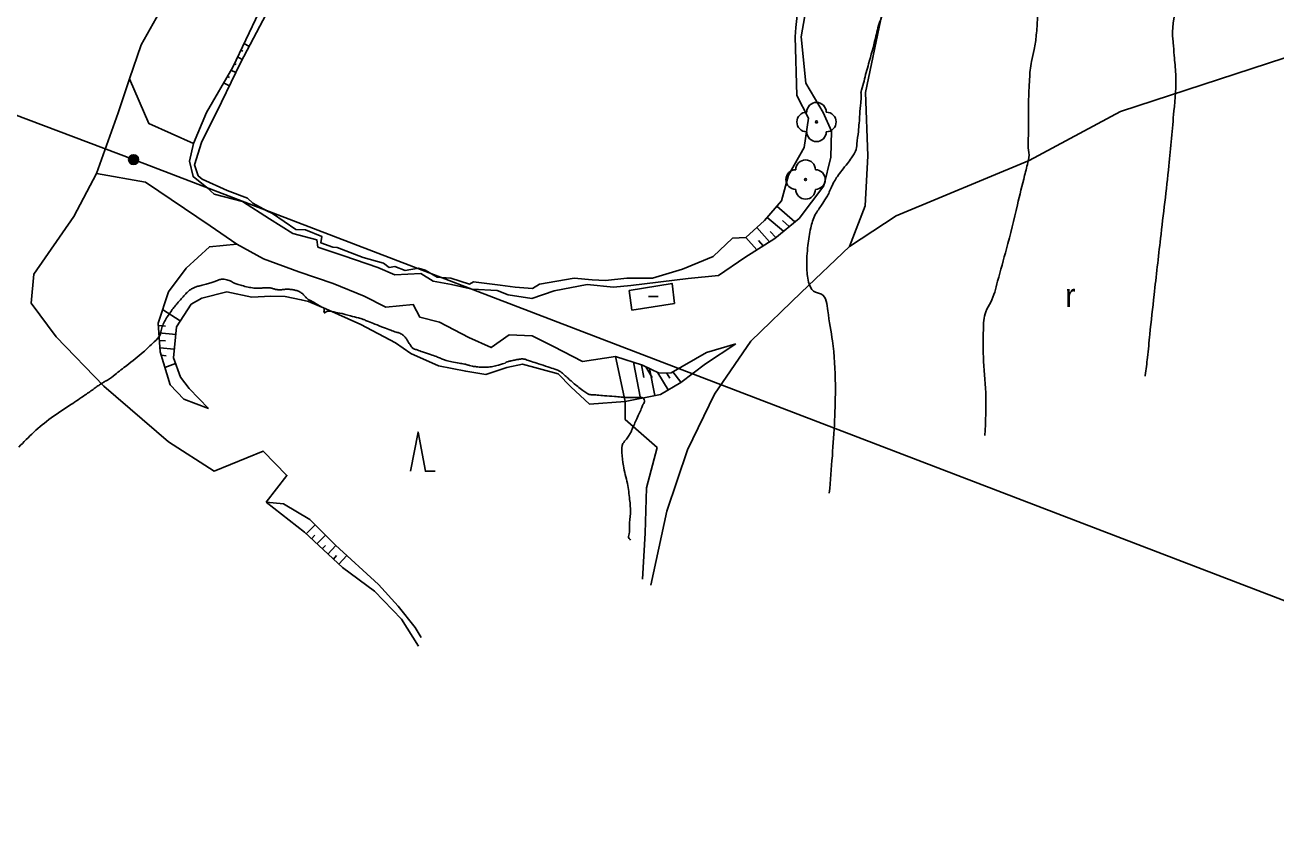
# Model space of a CAD drawing. Extents: x -475575 to -473225, y -1116053 to -1114104.
# Drawn here: x -474036.8 to -473909.2, y -1115920.9 to -1115838.9 of the extents above; entities that cross this region are included whole.
import ezdxf

# ---------------------------------------------------------------- set-up
doc = ezdxf.new("R2010")
doc.units = 0
doc.layers.add('Vrstevnice_vedlejsi', color=7, linetype='Continuous')
doc.layers.add('Vrstva_10', color=7, linetype='Continuous')

msp = doc.modelspace()

# ---------------------------------------------------------------- linework, layer by layer
at = {"layer": 'Vrstevnice_vedlejsi'}
for points in [[(-473849.08800000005, -1115665.384), (-473849.911, -1115667.105), (-473850.824, -1115668.952), (-473851.82800000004, -1115670.9270000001), (-473852.924, -1115673.0280000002), (-473853.94800000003, -1115674.8290000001), (-473854.9, -1115676.33), (-473855.78, -1115677.531), (-473856.701, -1115678.789), (-473857.663, -1115680.104), (-473858.666, -1115681.475), (-473858.526, -1115685.303), (-473857.244, -1115691.5860000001), (-473854.819, -1115700.3260000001), (-473853.38700000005, -1115707.367), (-473852.94700000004, -1115712.7110000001), (-473853.50100000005, -1115716.355), (-473856.753, -1115721.199), (-473862.70300000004, -1115727.2410000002), (-473871.352, -1115734.4810000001), (-473878.193, -1115740.057), (-473883.22900000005, -1115743.967), (-473886.457, -1115746.213), (-473888.69200000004, -1115748.0080000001), (-473889.93200000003, -1115749.3530000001), (-473890.178, -1115750.2480000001), (-473890.522, -1115751.3660000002), (-473890.96400000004, -1115752.709), (-473891.505, -1115754.276), (-473892.082, -1115755.84), (-473892.694, -1115757.399), (-473893.341, -1115758.955), (-473893.989, -1115760.3930000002), (-473894.63700000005, -1115761.712), (-473895.287, -1115762.912), (-473896.631, -1115765.4980000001), (-473898.67000000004, -1115769.469), (-473901.40400000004, -1115774.824), (-473903.569, -1115778.895), (-473905.163, -1115781.681), (-473906.18700000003, -1115783.182), (-473907.574, -1115785.885), (-473909.324, -1115789.789), (-473911.438, -1115794.894), (-473913.02400000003, -1115798.887), (-473914.082, -1115801.766), (-473914.614, -1115803.531), (-473915, -1115805.0150000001), (-473915.24100000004, -1115806.219), (-473915.337, -1115807.141), (-473915.885, -1115811.303), (-473916.884, -1115818.703), (-473918.335, -1115829.343), (-473919.30100000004, -1115836.442), (-473919.78400000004, -1115840.002), (-473919.783, -1115840.022), (-473919.73000000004, -1115840.673), (-473919.62600000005, -1115841.955), (-473919.47000000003, -1115843.869), (-473919.651, -1115847.62), (-473920.169, -1115853.208), (-473921.02400000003, -1115860.634), (-473921.672, -1115866.3660000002), (-473922.114, -1115870.405), (-473922.34900000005, -1115872.7510000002), (-473922.57300000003, -1115874.585), (-473922.581296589, -1115874.648507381)], [(-473938.93362807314, -1115880.720956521), (-473938.84300000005, -1115876.351), (-473939.08400000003, -1115872.702), (-473939.079, -1115869.948), (-473938.82800000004, -1115868.09), (-473938.331, -1115867.1260000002), (-473937.63, -1115864.989), (-473936.72400000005, -1115861.678), (-473935.614, -1115857.193), (-473934.87200000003, -1115854.198), (-473934.5, -1115852.693), (-473934.49700000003, -1115852.679), (-473934.495, -1115852.666), (-473934.493, -1115852.654), (-473934.492, -1115852.6430000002), (-473934.49000000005, -1115852.631), (-473934.488, -1115852.618), (-473934.484, -1115852.605), (-473934.48000000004, -1115851.618), (-473934.477, -1115849.658), (-473934.472, -1115846.723), (-473934.374, -1115844.361), (-473934.18000000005, -1115842.5720000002), (-473933.89200000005, -1115841.355), (-473933.68700000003, -1115839.875), (-473933.565, -1115838.1330000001), (-473933.525, -1115836.127), (-473933.31, -1115834.3360000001), (-473932.92100000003, -1115832.7580000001), (-473932.357, -1115831.395), (-473931.79500000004, -1115829.879), (-473931.23500000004, -1115828.213), (-473930.679, -1115826.395), (-473930.08300000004, -1115822.996), (-473929.44700000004, -1115818.016), (-473928.77300000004, -1115811.455), (-473928.24700000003, -1115806.61), (-473927.87, -1115803.4810000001), (-473927.64200000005, -1115802.0690000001), (-473927.36600000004, -1115800.502), (-473927.042, -1115798.78), (-473926.67100000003, -1115796.9030000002), (-473926.27900000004, -1115794.601), (-473925.86600000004, -1115791.872), (-473925.43200000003, -1115788.716), (-473925.036, -1115786.321), (-473924.67600000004, -1115784.686), (-473924.35400000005, -1115783.811), (-473923.89900000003, -1115782.575), (-473923.31100000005, -1115780.977), (-473922.59, -1115779.017), (-473922.106, -1115777.688), (-473921.859, -1115776.9910000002), (-473921.84900000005, -1115776.924), (-473921.84, -1115776.834), (-473921.832, -1115776.722), (-473921.824, -1115776.587), (-473921.80000000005, -1115776.462), (-473921.759, -1115776.348), (-473921.701, -1115776.244), (-473921.177, -1115775.487), (-473920.18600000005, -1115774.0790000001), (-473918.72900000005, -1115772.0180000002), (-473917.73000000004, -1115770.605), (-473917.19, -1115769.838), (-473917.108, -1115769.718), (-473917.05100000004, -1115769.632), (-473917.01800000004, -1115769.5820000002), (-473917.01, -1115769.566), (-473916.50200000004, -1115768.6260000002), (-473915.494, -1115766.762), (-473913.98600000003, -1115763.9740000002), (-473912.48000000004, -1115760.911), (-473911.1822816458, -1115758.0507802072)], [(-473954.7894387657, -1115886.609022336), (-473954.481, -1115882.779), (-473954.17500000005, -1115875.538), (-473954.47000000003, -1115871.0760000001), (-473954.938, -1115868), (-473955.579, -1115866.308), (-473956.39300000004, -1115866.0010000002), (-473956.897, -1115865.068), (-473957.09, -1115863.51), (-473956.973, -1115861.3260000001), (-473956.68100000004, -1115859.549), (-473956.216, -1115858.1770000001), (-473955.575, -1115857.21), (-473955.12, -1115856.493), (-473954.84900000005, -1115856.024), (-473954.764, -1115855.8050000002), (-473954.64, -1115855.527), (-473954.47900000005, -1115855.19), (-473954.27900000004, -1115854.796), (-473953.957, -1115854.2950000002), (-473953.51300000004, -1115853.6870000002), (-473952.946, -1115852.9710000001), (-473952.52300000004, -1115852.405), (-473952.245, -1115851.989), (-473952.11000000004, -1115851.723), (-473951.971, -1115850.965), (-473951.82700000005, -1115849.715), (-473951.68000000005, -1115847.972), (-473951.58400000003, -1115846.779), (-473951.54000000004, -1115846.135), (-473951.547, -1115846.041), (-473951.553, -1115845.946), (-473951.55700000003, -1115845.851), (-473951.559, -1115845.754), (-473951.55100000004, -1115845.661), (-473951.532, -1115845.5720000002), (-473951.50100000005, -1115845.487), (-473951.25100000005, -1115844.567), (-473950.78, -1115842.81), (-473950.08800000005, -1115840.219), (-473949.62700000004, -1115838.49), (-473949.396, -1115837.6260000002), (-473949.396, -1115837.624), (-473949.396, -1115837.622), (-473949.395, -1115837.62), (-473949.39400000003, -1115837.617), (-473949.146, -1115836.566), (-473948.64900000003, -1115834.467), (-473947.90400000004, -1115831.318), (-473947.407, -1115829.219), (-473947.158, -1115828.1700000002), (-473947.158, -1115828.169), (-473947.158, -1115828.168), (-473947.158, -1115828.1670000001), (-473947.157, -1115828.166), (-473947.157, -1115828.164), (-473947.157, -1115828.163), (-473947.156, -1115828.161), (-473946.77800000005, -1115827.246), (-473946.021, -1115825.4170000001), (-473944.88700000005, -1115822.675), (-473944.13, -1115820.8460000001), (-473943.75200000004, -1115819.931), (-473943.75200000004, -1115819.9300000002), (-473943.75100000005, -1115819.929), (-473943.75, -1115819.928), (-473943.749, -1115819.9270000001), (-473943.748, -1115819.926), (-473943.74700000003, -1115819.925), (-473943.74600000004, -1115819.925), (-473943.461, -1115819.017), (-473942.89200000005, -1115817.2010000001), (-473942.038, -1115814.4780000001), (-473941.451, -1115812.604), (-473941.13, -1115811.5790000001), (-473941.076, -1115811.4030000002), (-473941.047, -1115811.137), (-473941.041, -1115810.781)], [(-473994.22900000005, -1115872.945), (-473994.422, -1115872.837), (-473994.824, -1115872.673), (-473995.434, -1115872.455), (-473996.253, -1115872.183), (-473996.82700000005, -1115871.9880000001), (-473997.157, -1115871.872), (-473997.243, -1115871.834), (-473997.395, -1115871.654), (-473997.613, -1115871.3320000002), (-473997.897, -1115870.867), (-473998.216, -1115870.519), (-473998.569, -1115870.287), (-473998.956, -1115870.172), (-473999.51, -1115869.977), (-474000.22900000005, -1115869.703), (-474001.114, -1115869.35), (-474001.759, -1115869.093), (-474002.162, -1115868.933), (-474002.325, -1115868.869), (-474002.80600000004, -1115868.73), (-474003.60500000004, -1115868.516), (-474004.722, -1115868.226), (-474005.52400000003, -1115868.074), (-474006.009, -1115868.0590000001), (-474006.179, -1115868.181), (-474006.281, -1115868.203), (-474006.31600000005, -1115868.124), (-474006.282, -1115867.9440000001), (-474006.292, -1115867.8090000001), (-474006.346, -1115867.719), (-474006.444, -1115867.675), (-474006.63800000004, -1115867.566), (-474006.929, -1115867.3930000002), (-474007.31600000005, -1115867.1570000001), (-474007.601, -1115866.992), (-474007.783, -1115866.899), (-474007.864, -1115866.877), (-474008.00100000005, -1115866.771), (-474008.19700000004, -1115866.578), (-474008.45, -1115866.301), (-474008.745, -1115866.087), (-474009.082, -1115865.9370000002), (-474009.461, -1115865.851), (-474009.846, -1115865.807), (-474010.238, -1115865.806), (-474010.63700000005, -1115865.848), (-474011, -1115865.844), (-474011.32700000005, -1115865.7920000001), (-474011.618, -1115865.695), (-474011.98000000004, -1115865.646), (-474012.413, -1115865.647), (-474012.916, -1115865.696), (-474013.461, -1115865.675), (-474014.049, -1115865.583), (-474014.678, -1115865.4200000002), (-474015.17100000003, -1115865.27), (-474015.52800000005, -1115865.131), (-474015.75, -1115865.0050000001), (-474015.983, -1115864.9030000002), (-474016.227, -1115864.8260000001), (-474016.483, -1115864.774), (-474016.772, -1115864.786), (-474017.09400000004, -1115864.862), (-474017.449, -1115865.003), (-474017.859, -1115865.1400000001), (-474018.326, -1115865.276), (-474018.848, -1115865.408), (-474019.271, -1115865.534), (-474019.596, -1115865.654), (-474019.82200000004, -1115865.7680000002), (-474020.064, -1115865.943), (-474020.32200000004, -1115866.179), (-474020.596, -1115866.477), (-474020.878, -1115866.793), (-474021.169, -1115867.1260000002), (-474021.47000000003, -1115867.477), (-474021.78, -1115867.8800000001), (-474022.101, -1115868.3360000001), (-474022.43200000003, -1115868.844), (-474022.69100000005, -1115869.354), (-474022.878, -1115869.867), (-474022.994, -1115870.3830000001), (-474023.62100000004, -1115871.169), (-474024.76, -1115872.2280000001), (-474026.411, -1115873.558), (-474027.617, -1115874.5010000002), (-474028.378, -1115875.058), (-474028.693, -1115875.2280000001), (-474029.02300000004, -1115875.4300000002), (-474029.369, -1115875.663), (-474029.73000000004, -1115875.929), (-474030.64400000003, -1115876.561), (-474032.11000000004, -1115877.56), (-474034.128, -1115878.926), (-474035.902, -1115880.3760000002), (-474037.43100000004, -1115881.909)], [(-473975.06290085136, -1115891.391556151), (-473975.157, -1115891.245), (-473975.20800000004, -1115891.202), (-473975.211, -1115890.757), (-473975.166, -1115889.909), (-473975.07300000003, -1115888.6600000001), (-473975.145, -1115887.225), (-473975.381, -1115885.605), (-473975.783, -1115883.799), (-473975.93200000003, -1115882.442), (-473975.82800000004, -1115881.534), (-473975.471, -1115881.075), (-473975.196, -1115880.679), (-473975.004, -1115880.345), (-473974.89300000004, -1115880.074), (-473974.723, -1115879.681), (-473974.49100000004, -1115879.166), (-473974.2, -1115878.5280000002), (-473973.957, -1115877.984), (-473973.76300000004, -1115877.533), (-473973.618, -1115877.175), (-473973.738, -1115876.941), (-473974.124, -1115876.831), (-473974.775, -1115876.844), (-473975.239, -1115876.848), (-473975.516, -1115876.843), (-473975.60500000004, -1115876.827), (-473976.00100000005, -1115876.79), (-473976.70300000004, -1115876.7310000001), (-473977.712, -1115876.651), (-473978.46, -1115876.593), (-473978.94800000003, -1115876.558), (-473979.17500000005, -1115876.5450000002), (-473979.5, -1115876.402), (-473979.92100000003, -1115876.128), (-473980.44, -1115875.7240000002), (-473980.911, -1115875.337), (-473981.335, -1115874.967), (-473981.712, -1115874.6160000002), (-473982.00800000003, -1115874.355), (-473982.22500000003, -1115874.1840000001), (-473982.36100000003, -1115874.105), (-473982.777, -1115873.948), (-473983.473, -1115873.713), (-473984.45, -1115873.4000000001), (-473985.151, -1115873.171), (-473985.57800000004, -1115873.026), (-473985.73000000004, -1115872.965), (-473985.879, -1115872.925), (-473986.025, -1115872.904), (-473986.168, -1115872.9030000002), (-473986.408, -1115872.933), (-473986.745, -1115872.993), (-473987.179, -1115873.085), (-473987.50700000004, -1115873.1700000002), (-473987.72900000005, -1115873.2510000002), (-473987.84500000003, -1115873.3260000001), (-473988.113, -1115873.421), (-473988.53400000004, -1115873.536), (-473989.107, -1115873.671), (-473989.669, -1115873.744), (-473990.221, -1115873.754), (-473990.764, -1115873.702), (-473991.179, -1115873.647), (-473991.466, -1115873.588), (-473991.62700000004, -1115873.5250000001), (-473991.984, -1115873.438), (-473992.537, -1115873.327), (-473993.286, -1115873.19), (-473993.85000000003, -1115873.063), (-473994.22900000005, -1115872.945)]]:
    msp.add_spline(points, degree=3, dxfattribs=at)
at = {"layer": 'Vrstva_10'}
for p, q in [((-474014.4609299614, -1115840.7491937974), (-474013.9345895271, -1115841.0286887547)), ((-474015.1124322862, -1115842.1016026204), (-474014.63808012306, -1115842.3534909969)), ((-474014.78668112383, -1115841.425398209), (-474014.5865426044, -1115841.5316748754)), ((-474015.7980128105, -1115843.4601263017), (-474015.29955235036, -1115843.6995289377)), ((-474015.4472291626, -1115842.7965844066), (-474015.2582766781, -1115842.8873352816)), ((-474016.55470474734, -1115844.760734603), (-474015.9489611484, -1115845.0516636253)), ((-474016.17635877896, -1115844.1104304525), (-474015.9555179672, -1115844.216496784)), ((-473958.28931128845, -1115858.9221845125), (-473960.1345433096, -1115857.331656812)), ((-473959.465230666, -1115859.888914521), (-473961.1138857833, -1115858.4678294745)), ((-473958.87727097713, -1115859.4055495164), (-473959.5760484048, -1115858.803226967)), ((-473960.88452292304, -1115860.9537840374), (-473962.1892148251, -1115859.510246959)), ((-473960.2516760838, -1115860.5354557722), (-473960.80412613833, -1115859.9242140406)), ((-473962.17069991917, -1115861.7676929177), (-473963.302, -1115860.516)), ((-473961.5276357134, -1115861.36075385), (-473962.01483279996, -1115860.8217093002)), ((-473973.23263136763, -1115866.5248458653), (-473972.23263136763, -1115866.5248458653)), ((-474022.7585123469, -1115867.8681098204), (-474020.9656823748, -1115869.0342220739)), ((-474023.2030597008, -1115869.4959401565), (-474022.46715973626, -1115869.5643088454)), ((-474023.15249645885, -1115870.2538675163), (-474021.4326896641, -1115870.4136459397)), ((-474023.1019332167, -1115871.011794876), (-474022.4619877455, -1115871.0712489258)), ((-474023.0513699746, -1115871.7697222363), (-474021.57144941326, -1115871.9072140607)), ((-474022.9115683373, -1115872.5359402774), (-474022.4032727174, -1115872.5831634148)), ((-474022.5349571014, -1115873.7675212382), (-474021.4398950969, -1115873.3655573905)), ((-473974.76820279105, -1115873.2404078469), (-473974.05179164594, -1115876.929359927)), ((-473973.953750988, -1115873.5001311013), (-473973.6984694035, -1115874.8146298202)), ((-473973.499592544, -1115873.7035206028), (-473972.845638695, -1115874.799606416)), ((-473973.1132091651, -1115873.8941973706), (-473972.5793024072, -1115876.64339587)), ((-473972.2618080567, -1115874.3143562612), (-473971.2206316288, -1115876.0594621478)), ((-473971.3746949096, -1115874.337435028), (-473971.0554390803, -1115874.8725366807)), ((-473970.73467034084, -1115874.221375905), (-473969.93306253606, -1115875.2900461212)), ((-474008.1333898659, -1115890.7238130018), (-474007.2214481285, -1115889.8087314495)), ((-474007.58488777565, -1115891.235910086), (-474007.22701563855, -1115890.8768057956)), ((-474007.0363856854, -1115891.7480071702), (-474006.15896673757, -1115890.8675672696)), ((-474006.4878835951, -1115892.2601042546), (-474006.1438205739, -1115891.9148566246)), ((-474005.9034530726, -1115892.8057451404), (-474005.09518012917, -1115891.9250383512)), ((-474005.3552222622, -1115893.31758895), (-474005.03017901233, -1115892.9634167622)), ((-474004.80699145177, -1115893.82943276), (-474003.9900481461, -1115892.9392786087))]:
    msp.add_line(p, q, dxfattribs=at)
for points in [[(-473952.745, -1115861.4510000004), (-473951.12100000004, -1115857.277), (-473950.868, -1115852.21), (-473951.092, -1115845.73), (-473949.386, -1115837.624), (-473947.14800000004, -1115828.1670000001), (-473943.74000000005, -1115819.9300000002), (-473938.797, -1115811.358), (-473934.109, -1115801.249), (-473929.51900000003, -1115792.486), (-473925.151, -1115785.121), (-473920.961, -1115776.943), (-473917.065, -1115769.5660000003), (-473914.032, -1115761.243), (-473912.99859636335, -1115758.4091251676)], [(-474150.74251039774, -1115805.3141756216), (-474025.7250000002, -1115852.5750000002), (-473847.43900000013, -1115920.9400000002)], [(-474026.12600000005, -1115844.347), (-474024.96300000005, -1115840.8900000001), (-474021.571, -1115834.8490000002), (-474017.47000000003, -1115827.28), (-474013.11000000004, -1115817.5550000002)], [(-473839.434, -1115830.335), (-473845.478, -1115829.942), (-473853.02900000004, -1115829.374), (-473860.819, -1115829.4680000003), (-473868.869, -1115829.172), (-473874.61500000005, -1115829.686), (-473879.109, -1115831.7720000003), (-473888.26, -1115834.6260000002), (-473898.36600000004, -1115838.2010000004), (-473908.342, -1115842.205), (-473925.08800000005, -1115847.665), (-473934.406, -1115852.6670000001), (-473947.971, -1115858.298), (-473952.745, -1115861.4510000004), (-473957.669, -1115866.1330000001), (-473962.799, -1115871.094), (-473966.481, -1115876.513), (-473969.234, -1115882.19), (-473971.37100000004, -1115888.415), (-473972.981, -1115895.9810000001)], [(-474019.631, -1115850.925), (-474018.302, -1115847.764), (-474015.617, -1115843.149), (-474012.94, -1115837.592), (-474012.8089742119, -1115837.0913641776)], [(-473957.94200000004, -1115836.655), (-473958.216, -1115839.118), (-473958.276, -1115840.074), (-473958.098, -1115846.057), (-473956.927, -1115848.3460000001), (-473957.368, -1115851.337), (-473958.95300000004, -1115854.161), (-473959.65300000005, -1115856.773), (-473961.389, -1115858.787), (-473963.302, -1115860.516), (-473964.651, -1115860.578), (-473966.62100000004, -1115862.446), (-473969.772, -1115863.747), (-473972.803, -1115864.683), (-473975.43200000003, -1115864.6640000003), (-473977.623, -1115864.905), (-473978.956, -1115864.8320000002), (-473980.794, -1115864.683), (-473984.336, -1115865.288), (-473985.06600000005, -1115865.736), (-473986.83300000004, -1115865.5860000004), (-473988.352, -1115865.375), (-473991.054, -1115865.043), (-473991.473, -1115865.2750000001), (-473993.374, -1115864.665), (-473994.755, -1115864.5830000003), (-473996.003, -1115863.858), (-473996.663, -1115863.6470000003), (-473998.02900000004, -1115863.8730000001), (-473999.098, -1115863.475), (-473999.661, -1115863.567), (-474000.242, -1115863.136), (-474002.31200000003, -1115862.568), (-474004.978, -1115861.533), (-474005.408, -1115861.4980000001), (-474006.617, -1115861.0720000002), (-474006.514, -1115860.4270000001), (-474008.20200000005, -1115859.744), (-474009.172, -1115859.719), (-474011.56, -1115858.081), (-474012.129, -1115857.817), (-474013.579, -1115857.019), (-474014.119, -1115856.514), (-474016.18700000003, -1115855.7450000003), (-474018.737, -1115854.5760000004), (-474019.128, -1115854.223), (-474019.50200000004, -1115853.1200000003), (-474018.79600000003, -1115850.834), (-474016.756, -1115846.732), (-474014.79500000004, -1115842.649), (-474011.89300000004, -1115837.1840000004)], [(-473957.047, -1115836.574), (-473957.64800000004, -1115840.065), (-473957.178, -1115844.791), (-473955.419, -1115847.7620000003), (-473954.58, -1115849.685), (-473954.64200000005, -1115852.324), (-473955.346, -1115855.267), (-473957.867, -1115858.575), (-473960.346, -1115860.6130000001), (-473963.418, -1115862.557), (-473966.075, -1115864.3830000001), (-473969.184, -1115864.696), (-473975.01700000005, -1115865.4310000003), (-473976.78, -1115865.585)], [(-474029.4930000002, -1115853.98), (-474027.28900000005, -1115847.804), (-474026.12600000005, -1115844.3469999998)], [(-474026.12600000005, -1115844.347), (-474024.15799999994, -1115848.906), (-474019.63099999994, -1115850.9249999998)], [(-473976.78, -1115865.585), (-473979.462, -1115865.301), (-473982.831, -1115865.977), (-473985.134, -1115866.7380000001), (-473987.543, -1115866.355), (-473988.646, -1115865.942), (-473991.188, -1115865.786), (-473993.30100000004, -1115865.3220000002), (-473995.173, -1115864.987), (-473996.429, -1115864.2080000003), (-473999.07300000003, -1115864.324), (-474000.81200000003, -1115863.5890000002), (-474004.283, -1115862.375), (-474006.93700000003, -1115861.506), (-474007.02900000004, -1115860.7720000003), (-474009.5, -1115860.0990000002), (-474011.851, -1115858.618), (-474014.61500000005, -1115856.8360000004), (-474017.514, -1115856.0990000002), (-474018.243, -1115855.415), (-474019.661, -1115854.318), (-474020.02800000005, -1115852.752), (-474019.631, -1115850.925)], [(-474022.174, -1115881.354), (-474028.74000000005, -1115875.675), (-474033.60400000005, -1115870.646), (-474036.15400000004, -1115867.2140000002), (-474035.89900000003, -1115864.2580000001), (-474031.832, -1115858.3930000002), (-474029.493, -1115853.98), (-474024.50700000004, -1115854.877), (-474017.905, -1115859.338), (-474015.21300000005, -1115861.2070000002)], [(-474015.21300000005, -1115861.2070000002), (-474017.98500000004, -1115861.469), (-474020.35500000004, -1115863.6400000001), (-474022.16500000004, -1115866.078), (-474023.21900000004, -1115869.257), (-474023.025, -1115872.165), (-474021.99600000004, -1115875.53), (-474020.61500000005, -1115876.994), (-474018.075, -1115877.975)], [(-473976.582, -1115872.662), (-473979.96400000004, -1115873.179), (-473982.895, -1115871.646), (-473985.102, -1115870.563), (-473987.42600000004, -1115870.4410000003), (-473989.277, -1115871.7510000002), (-473991.538, -1115870.7080000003), (-473994.51900000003, -1115869.1430000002), (-473996.53, -1115868.6570000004), (-473997.212, -1115867.367), (-474000.006, -1115867.6200000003), (-474002.22500000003, -1115866.506), (-474005.358, -1115865.219), (-474008.88200000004, -1115864.023), (-474012.473, -1115862.712), (-474015.21300000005, -1115861.2070000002)], [(-473964.30600000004, -1115871.368), (-473967.4, -1115873.3900000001), (-473969.94100000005, -1115875.296), (-473972.016, -1115876.534), (-473975.60500000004, -1115877.2310000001), (-473979.238, -1115877.516), (-473981.15400000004, -1115875.739), (-473982.428, -1115874.4370000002), (-473986.063, -1115873.449), (-473987.655, -1115873.784), (-473989.81200000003, -1115874.484), (-473991.851, -1115874.161), (-473994.64, -1115873.622), (-473997.467, -1115872.3390000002), (-473999.011, -1115871.28), (-474002.554, -1115869.379), (-474006.131, -1115867.808), (-474007.88, -1115867.0490000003), (-474008.62600000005, -1115866.874), (-474010.26800000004, -1115866.543), (-474011.734, -1115866.496), (-474013.684, -1115866.594), (-474016.21900000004, -1115866.077), (-474018.75700000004, -1115866.7210000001), (-474019.852, -1115867.3220000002), (-474021.36100000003, -1115869.642), (-474021.65300000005, -1115872.7850000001), (-474020.924, -1115874.771), (-474020.06700000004, -1115875.932), (-474018.075, -1115877.975)], [(-473964.30600000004, -1115871.368), (-473967.32700000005, -1115872.2350000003), (-473970.897, -1115874.3160000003), (-473972.145, -1115874.372), (-473973.835, -1115873.538), (-473976.582, -1115872.662)], [(-473973.83900000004, -1115895.3560000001), (-473973.581, -1115890.662), (-473973.412, -1115886.0560000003), (-473972.353, -1115881.9300000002), (-473975.59, -1115879.097), (-473975.60500000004, -1115877.2310000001), (-473976.582, -1115872.662)], [(-473997.47400000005, -1115884.3630000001), (-473996.71400000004, -1115880.3630000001), (-473995.97400000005, -1115884.3630000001), (-473994.97400000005, -1115884.3630000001)], [(-474012.211, -1115887.519), (-474010.096, -1115884.7820000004), (-474012.52300000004, -1115882.2990000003), (-474017.52, -1115884.347), (-474022.174, -1115881.354)], [(-474012.211, -1115887.519), (-474008.281, -1115890.5860000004), (-474004.439, -1115894.173), (-474001.16000000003, -1115896.581), (-473998.39400000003, -1115899.436), (-473996.68600000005, -1115902.196)], [(-474012.211, -1115887.519), (-474010.439, -1115887.6810000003), (-474007.75200000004, -1115889.28), (-474005.129, -1115891.894), (-474000.764, -1115895.9000000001), (-473998.753, -1115898.111), (-473997.03, -1115900.284), (-473996.401, -1115901.31)]]:
    msp.add_lwpolyline(points, dxfattribs=at)
msp.add_lwpolyline([(-473974.924, -1115867.946), (-473970.58, -1115867.239), (-473970.819, -1115865.2010000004), (-473975.18600000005, -1115865.929)], close=True, dxfattribs=at)
for centre, radius in [((-473956.096, -1115848.7410000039), 0.09999906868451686), ((-474025.72500000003, -1115852.575), 0.49999534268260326), ((-474025.72500000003, -1115852.575), 0.3999962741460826), ((-474025.72500000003, -1115852.575), 0.29999720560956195), ((-474025.72500000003, -1115852.575), 0.1999981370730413), ((-474025.72500000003, -1115852.575), 0.09999906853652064), ((-473957.207, -1115854.6100000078), 0.09999906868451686)]:
    msp.add_circle(centre, radius, dxfattribs=at)
for centre, radius, start, end in [((-473956.096, -1115847.7410093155), 0.9999906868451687, 0, 180), ((-473957.09599068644, -1115848.7410000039), 0.9999906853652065, 90, 270), ((-473955.0960093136, -1115848.7410000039), 0.9999906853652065, 270, 89.99999999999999), ((-473956.096, -1115849.7409906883), 0.9999906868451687, 180, 0), ((-473958.2069906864, -1115854.6100000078), 0.9999906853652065, 90, 270), ((-473957.207, -1115853.6100093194), 0.9999906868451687, 0, 180), ((-473956.2070093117, -1115854.6100000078), 0.9999906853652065, 270, 89.99999999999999), ((-473957.207, -1115855.6099906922), 0.9999906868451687, 180, 0)]:
    msp.add_arc(centre, radius, start, end, dxfattribs=at)

# ---------------------------------------------------------------- texts
msp.add_text('r', height=2.399976, dxfattribs=at).set_placement((-473930.75700000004, -1115867.622))

doc.saveas('drawing.dxf')
